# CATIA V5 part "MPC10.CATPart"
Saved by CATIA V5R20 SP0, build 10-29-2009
Part number: MPC10
Definition: NONE
Nomenclature: MPC10
Source: Unknown
Description: MPC10
Bounding box of the stored display mesh (mm): x 0 to 12, y -5 to 5, z -5 to 5
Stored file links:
  C:\Users\Utente\Desktop\IO LAVORO\3D X SITO CF\X SITO\PLASTICA\CFMR\MPC10.CATPart
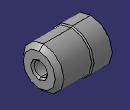
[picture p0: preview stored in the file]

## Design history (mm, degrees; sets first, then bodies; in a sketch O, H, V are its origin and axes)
Body1 "MPC10" (main body)
  Solid1: solid without history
